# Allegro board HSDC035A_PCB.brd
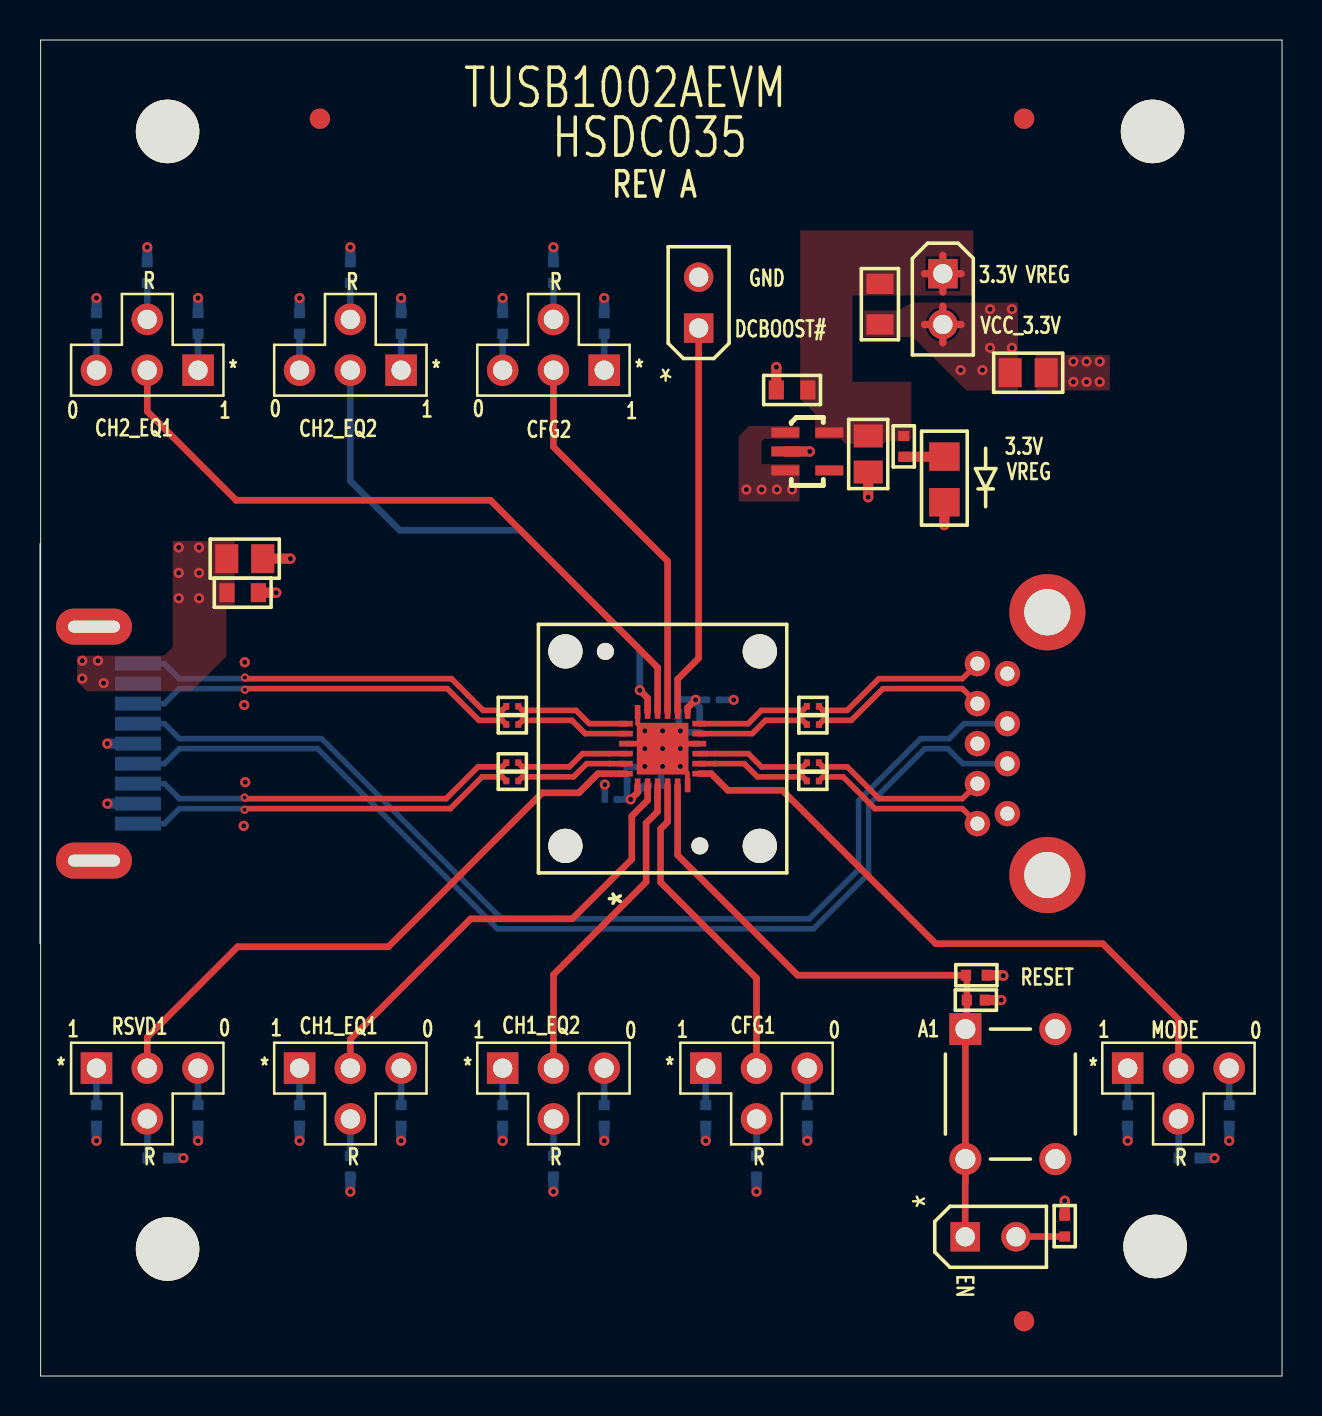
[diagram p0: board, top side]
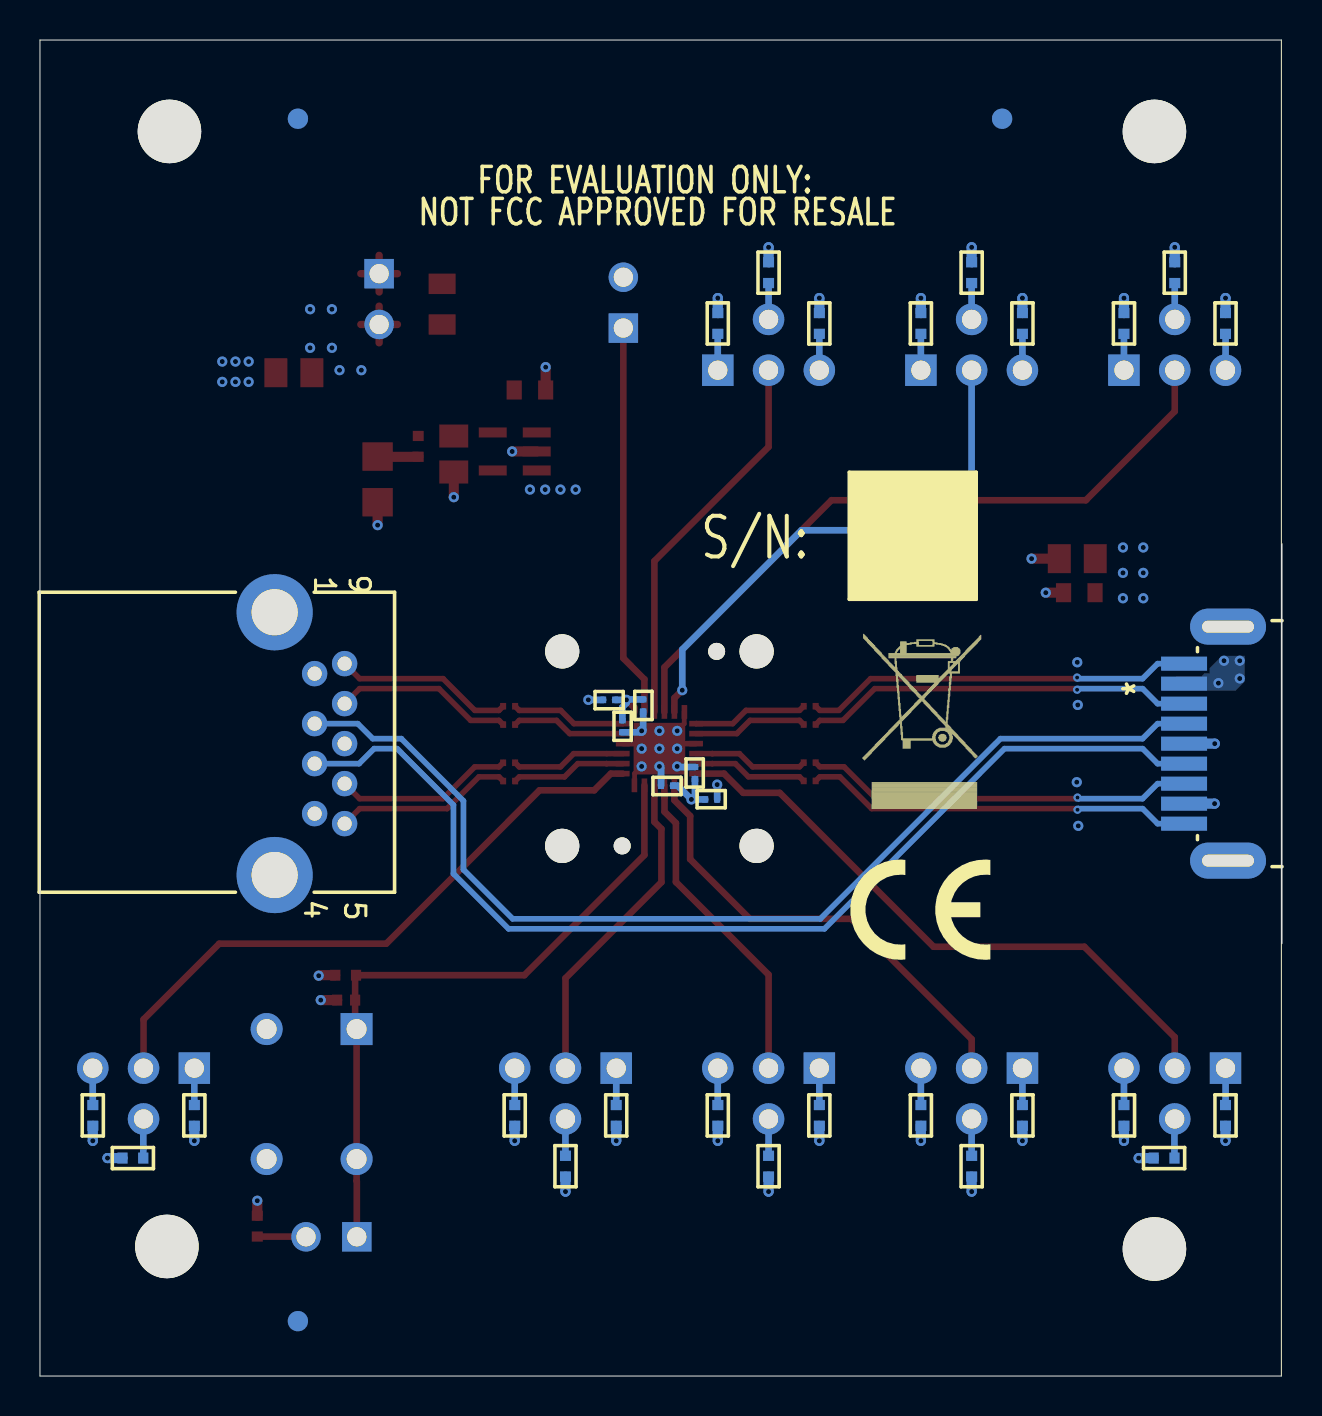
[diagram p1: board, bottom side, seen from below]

Outline 62.14 x 66.8 mm; copper layers: TOP, L2_GND, L3_PWR, BOTTOM. Coordinates in mm from the lower left corner of the outline.
Outline path: 0.03,66.8 62.14,66.8 62.14,0 0.03,0 0.03,66.8

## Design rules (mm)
net group DIFFPAIR0: nets N16632710 N16632722
net group DIFFPAIR2: nets USB2_DM USB2_DP
net group DIFFPAIR4: nets TX2N_CONN TX2P_CONN
net group DIFFPAIR5: nets TX1N TX1P
net group DIFFPAIR6: nets TX2N TX2P
net group DIFFPAIR7: nets N16640066 N16640078
net group DIFFPAIR8: nets N16640110 N16640114
net group DIFFPAIR9: nets N16640070 N16640074
net group DIFFPAIR10: nets N16640102 N16640106

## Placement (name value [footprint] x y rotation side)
C1  0.1uF  [C0201]  23.63 30.67 0 top
C2  0.1uF  [C0201]  23.63 29.75 0 top
C3  0.1uF  [C0201]  38.67 33.49 0 top
C4  0.1uF  [C0201]  38.67 32.57 0 top
C5  10uF  [C0805]  10.24 40.87 0 top
C6  10uF  [C0805]  41.44 46.1 270 top
C7  1uf  [C0603]  10.14 39.17 0 top
C8  1uf  [C0603]  37.63 49.3 180 top
C9  1uF  [C0201]  29.37 30.15 90 bottom
C10  1uF  [C0201]  33 32.49 270 bottom
C11  0.1uF  [C0201]  30.77 29.51 0 bottom
C12  0.1uF  [C0201]  33.66 33.81 0 bottom
C13  0.01uF  [C0201]  28.56 28.83 180 bottom
C14  0.01uF  [C0201]  31.96 33.53 270 bottom
C15  22uF  [C0805]  49.44 50.16 0 top
C16  220nF  [C0402]  46.82 18.8 0 top
C17  220nF  [C0201]  38.67 30.66 0 top
C18  220nF  [C0201]  38.67 29.75 0 top
C19  220nF  [C0201]  23.63 33.49 0 top
C20  220nF  [C0201]  23.63 32.57 0 top
D1  LED Green 0805  [LED_0805]  45.25 44.83 90 top
J1  HDR2X1 M .1  [HDR_THVT_1X2_100]  46.29 6.96 90 top
J2  HDR2X1 M .1  [HDR_THVT_1X2_100]  32.95 52.4 180 top
J3  HDR2X1 M .1  [HDR_THVT_1X2_100]  45.17 55.12 0 top
JMP1  4 Pin-T Berg Jumper  [BERG2X3TEE]  12.99 15.39 0 top
JMP2  4 Pin-T Berg Jumper  [BERG2X3TEE]  23.15 15.39 0 top
JMP3  4 Pin-T Berg Jumper  [BERG2X3TEE]  33.31 15.39 0 top
JMP4  4 Pin-T Berg Jumper  [BERG2X3TEE]  54.41 15.39 0 top
JMP5  4 Pin-T Berg Jumper  [BERG2X3TEE]  7.91 50.29 180 top
JMP6  4 Pin-T Berg Jumper  [BERG2X3TEE]  18.07 50.29 180 top
JMP7  4 Pin-T Berg Jumper  [BERG2X3TEE]  2.83 15.39 0 top
JMP8  4 Pin-T Berg Jumper  [BERG2X3TEE]  28.23 50.29 180 top
NOREF  -  []  0.03 66.8 0 top
NOREF#2  -  [unnamed#2]  49.23 2.74 0 top
NOREF#3  -  [unnamed#2]  14 62.87 0 top
NOREF#4  -  []  0.03 0 0 top
NOREF#5  -  []  12.66 0.86 0 top
NOREF#6  -  []  62.14 0 90 top
NOREF#7  -  []  88.93 38.1 0 top
NOREF#8  -  [unnamed#2]  49.23 62.87 0 top
NOREF#9  -  [unnamed#2]  6.38 6.35 0 top
NOREF#10  -  [unnamed#2]  6.38 62.23 0 top
NOREF#11  -  [unnamed#2]  55.66 62.23 0 top
NOREF#12  -  [unnamed#2]  55.79 6.48 0 top
NOREF#13  -  []  -3.78 -69.85 0 top
NOREF#14  -  []  18.09 23.32 180 bottom
NOREF#15  -  [unnamed#2]  14 62.87 180 bottom
NOREF#16  -  []  28.63 42.01 180 bottom
NOREF#17  -  [unnamed#2]  49.23 2.74 180 bottom
NOREF#18  -  [unnamed#2]  49.23 62.87 180 bottom
NOREF#19  -  []  17.99 33.93 180 bottom
NOREF#20  -  []  30.92 5.31 180 bottom
P1  USB3_STANDARD_TYPE_A_PLUG  [CON_SMRT_USB3A_AMP]  2.7 31.62 90 bottom
P2  USB3 Type A Receptacle  [USB3_TYPEA]  46.9 31.62 270 bottom
R1  1k  [R0402]  12.99 13.03 270 bottom
R2  20k  [R0402]  15.53 10.49 270 bottom
R3  1k  [R0402]  18.07 13.03 270 bottom
R4  1k  [R0402]  23.15 13.03 270 bottom
R5  20k  [R0402]  25.69 10.49 270 bottom
R6  1k  [R0402]  28.23 13.03 270 bottom
R7  1k  [R0402]  7.91 52.63 90 bottom
R8  20k  [R0402]  5.37 55.17 90 bottom
R9  1k  [R0402]  2.83 52.63 90 bottom
R10  1k  [R0402]  18.07 52.63 90 bottom
R11  20k  [R0402]  15.53 55.17 90 bottom
R12  1k  [R0402]  12.99 52.63 90 bottom
R13  1k  [R0402]  33.31 13.03 270 bottom
R14  20k  [R0402]  35.85 10.49 270 bottom
R15  1k  [R0402]  38.39 13.03 270 bottom
R16  1k  [R0402]  2.83 13.03 270 bottom
R17  20k  [R0402]  5.9 10.9 0 bottom
R18  1k  [R0402]  7.91 13.03 270 bottom
R19  1k  [R0402]  54.41 13.03 270 bottom
R20  20k  [R0402]  57.49 10.9 0 bottom
R21  1k  [R0402]  59.49 13.03 270 bottom
R22  1k  [R0402]  28.23 52.63 90 bottom
R23  20k  [R0402]  25.69 55.17 90 bottom
R24  1k  [R0402]  23.15 52.63 90 bottom
R25  1k  [R0402]  51.26 7.49 90 top
R26  0 Ohm  [R0805]  42.02 53.59 270 top
R27  20k  [R0402]  46.85 20.04 180 top
R28  300 Ohm  [R0402]  43.21 46.48 270 top
SW1  Switch - Push Button  [SW_THVT_EVQPAX05]  48.55 14.1 0 top
U1  TUSB1002ARGE  [SKT_TUSB1002RGE]  31.15 31.37 90 top
U2  LP5907  [DBV_R-PDSO-G5]  38.39 46.23 0 top

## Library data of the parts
C1-C4 C9-C14 C17-C20 = cc0201
C5 C6 C15 = cc0805
C7 C8 = cc0603 1.0uf 25V
C16 = cc0402
D1 = LED Green 0805_0
J1-J3 = HDR2X1 M .1
JMP1-JMP8 = 4 Pin-T Berg Jumper_0
P1 = USB3_STANDARD_TYPE_A_PLUG_0
P2 = USB 3.0 Type A Receptacle
R1-R25 R27 R28 = r0402
R26 = r0805
SW1 = Switch - Push Button_0
U1 = TUSB1002RGE_0
U2 = LP5907

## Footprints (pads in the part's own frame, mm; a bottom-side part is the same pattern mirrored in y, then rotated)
BERG2X3TEE
  rect 1.575x1.575 hole 0.965: 1(0,0)
  round 1.575 hole 0.965: 2(2.54,0) 3(5.08,0) 4(2.54,-2.54)
C0201
  rect 0.3x0.33 smd: 1(-0.3,0) 2(0.3,0)
C0402
  rect 0.51x0.55 smd: 1(-0.45,0) 2(0.45,0)
C0603
  rect 0.76x0.95 smd: 1(-0.787,0) 2(0.787,0)
C0805
  rect 1.15x1.45 smd: 1(-0.9,0) 2(0.9,0)
CON_SMRT_USB3A_AMP
  rect 0.7x2.3 smd: 1(3,2.2) 2(1,2.2) 3(-1,2.2) 4(-3,2.2) 5(-4,2.2) 6(-2,2.2) 7(0,2.2) 8(2,2.2) 9(4,2.2)
  oval 1.8x3.8 hole 0.6x2.6: 10(-5.85,0) 11(5.85,0)
DBV_R-PDSO-G5
  rect 1.4x0.5 smd: 1(-1.1,0.95) 2(-1.1,0) 3(-1.1,-0.95) 4(1.1,-0.95) 5(1.1,0.95)
HDR_THVT_1X2_100
  rect 1.473x1.473 hole 0.965: 1(0,0)
  round 1.473 hole 0.965: 2(0,-2.54)
LED_0805
  rect 1.422x1.524 smd: 1(-1.143,0) 2(1.143,0)
R0402
  rect 0.51x0.55 smd: 1(-0.52,0) 2(0.52,0)
R0805
  rect 1.02x1.35 smd: 1(-1.016,0) 2(1.016,0)
SKT_TUSB1002RGE
  round 1.71 hole 1.71 unplated: (-4.863,4.863) (-4.863,-4.863) (4.863,4.863) (4.863,-4.863)
  round 0.85 hole 0.85 unplated: (-4.863,-1.863) (4.863,2.863)
  rect 0.69x0.28 smd: 1(-1.835,1.25) 2(-1.835,0.75) 3(-1.835,0.25) 4(-1.835,-0.25) 5(-1.835,-0.75) 6(-1.835,-1.25) 13(1.835,-1.25) 14(1.835,-0.75) 15(1.835,-0.25) 16(1.835,0.25) 17(1.835,0.75) 18(1.835,1.25)
  rect 0.28x0.69 smd: 7(-1.25,-1.835) 8(-0.75,-1.835) 9(-0.25,-1.835) 10(0.25,-1.835) 11(0.75,-1.835) 12(1.25,-1.835) 19(1.25,1.835) 20(0.75,1.835) 21(0.25,1.835) 22(-0.25,1.835) 23(-0.75,1.835) 24(-1.25,1.835)
  rect 2.58x2.58 smd: 25(0,0)
SW_THVT_EVQPAX05
  rect 1.6x1.6 hole 1: A1(-2.25,3.25)
  round 1.6 hole 1: A2(-2.25,-3.25) B1(2.25,3.25) B2(2.25,-3.25)
unnamed#2
  round 1.016 smd: (0,0)
USB3_TYPEA
  round 1.27 hole 0.711: 1(-3.5,-1.5) 2(-1,-1.5) 3(1,-1.5) 4(3.5,-1.5) 5(4,0) 6(2,0) 7(0,0) 8(-2,0) 9(-4,0)
  round 3.81 hole 2.311: 10(-6.57,-3.5) 11(6.57,-3.5)

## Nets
3.3V: C6.1 C8.1 J3.1 R26.1 R28.1 U2.5(VOUT)
GND: C5.2 C6.2 C7.2 C8.2 C9.2 C10.2 C11.2 C12.2 C13.2 C14.2 C15.2 C16.2 D1.1(CATHODE) J2.2 P1.4(GND#4) P1.7(GND_SHIELD) P1.10(GND#10) P1.11(GND#11) P2.4(GND) P2.7(GND_DRAIN) P2.10(SHIELD1) P2.11(SHIELD2) R2.2 R3.2 R5.2 R6.2 R8.2 R9.2 R11.2 R12.2 R14.2 R15.2 R17.2 R18.2 R20.2 R21.2 R23.2 R24.2 R25.2 SW1.B1 SW1.B2(B) U1.6(GND#6) U1.10(GND#10) U1.18(GND#18) U1.21(GND#21) U1.25(PAD) U2.2(GND)
VBUS: C5.1 C7.1 P1.1(VBUS) P2.1(VBUS) U2.1(VIN) U2.3(EN)
VCC_3.3V: C9.1 C10.1 C11.1 C12.1 C13.1 C14.1 C15.1 J3.2 R1.2 R4.2 R7.2 R10.2 R13.2 R16.2 R19.2 R22.2 R26.2 R27.1 U1.1(VCC#1) U1.13(VCC#13)
CFG1: JMP3.2 U1.4(CFG1)
CFG2: JMP8.2 U1.15(CFG2)
CH1_EQ1: JMP1.2 U1.2(CH1_EQ1)
CH1_EQ2: JMP2.2 U1.3(CH1_EQ2)
CH2_EQ1: JMP5.2 U1.16(CH2_EQ1)
CH2_EQ2: JMP6.2 U1.17(CH2_EQ2)
DCBOOST#: J2.1 U1.14(DCBOOST#)
EN: C16.1 J1.1 R27.2 SW1.A1 SW1.A2(A) U1.5(EN)
MODE: JMP4.2 U1.7(MODE)
RSVD1: JMP7.2 U1.24(RSVD1)
TX1N: C2.2 U1.23(TX1N)
TX1P: C1.2 U1.22(TX1P)
TX2N: C4.1 U1.11(TX2N)
TX2N_CONN: C4.2 P2.8(SS_TX_N)
TX2P: C3.1 U1.12(TX2P)
TX2P_CONN: C3.2 P2.9(SS_TX_P)
USB2_DM: P1.2(DM) P2.2(USB2_DM)
USB2_DP: P1.3(DP) P2.3(USB2_DP)
N04063: JMP1.1 R1.1
N04069: JMP1.4 R2.1
N04079: JMP1.3 R3.1
N04162: JMP2.1 R4.1
N04168: JMP2.4 R5.1
N04172: JMP2.3 R6.1
N04828: JMP3.4 R14.1
N05600: JMP7.4 R17.1
N05896: J1.2 R25.1
N16532433: D1.2(ANNODE) R28.2
N16632710: C2.1 P1.5(SSRXN)
N16632722: C1.1 P1.6(SSRXP)
N16635768: JMP3.3 R15.1
N16635786: JMP3.1 R13.1
N16636225: JMP4.4 R20.1
N16636229: JMP4.1 R19.1
N16636241: JMP4.3 R21.1
N16636785: JMP5.4 R8.1
N16636789: JMP5.3 R9.1
N16636801: JMP5.1 R7.1
N16637091: JMP6.1 R10.1
N16637103: JMP6.3 R12.1
N16637121: JMP6.4 R11.1
N16637440: JMP7.1 R16.1
N16637452: JMP7.3 R18.1
N16637756: JMP8.1 R22.1
N16637768: JMP8.3 R24.1
N16637780: JMP8.4 R23.1
N16640066: C19.2 U1.19(RX2P)
N16640070: C19.1 P1.9(SSTXP)
N16640074: C20.1 P1.8(SSTXN)
N16640078: C20.2 U1.20(RX2N)
N16640102: C17.2 P2.6(SS_RX_P)
N16640106: C18.2 P2.5(SS_RX_N)
N16640110: C18.1 U1.8(RX1N)
N16640114: C17.1 U1.9(RX1P)

Pads without a net: U2 4

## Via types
v1: diameter 0.406, hole 0.203, TOP to BOTTOM, 4 vias
v2: diameter 0.508, hole 0.254, TOP to BOTTOM, 79 vias

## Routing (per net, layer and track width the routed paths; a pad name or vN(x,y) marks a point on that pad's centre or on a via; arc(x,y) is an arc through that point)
3.3V: length 3.7
  TOP w0.368: 44.25,55.12 J3.1 ; J3.1 46.08,55.12 ; J3.1 45.17,56.03 ; J3.1 45.17,54.2
GND: length 75.7
  TOP w0.241: U1.18 29.91,33.2 29.91,32.61 v2(30.26,32.26) ; v2(32.04,30.48) 32.39,30.13 32.39,29.54 U1.6
  TOP w0.279: U1.10 32.29,31.62 v2(32.04,31.37) ; v2(30.26,31.37) 30.21,31.37 29.96,31.62 U1.21
  TOP w0.508: D1.1 v2(45.25,42.55) ; C16.2 v2(48.09,18.8) ; R25.2 v2(51.26,8.76) ; v2(36.84,50.44) 36.84,50.44 C8.2 ; C5.2 v2(12.53,40.87) ; C7.2 v2(11.82,39.17) ; C6.2 v2(41.44,43.94) ; U2.2 v2(38.51,46.23)
  L2_GND w0.241: P1.11 4.78,37.47 ; P1.11 2.7,38.55 ; P1.11 2.7,36.39 ; 48.4,27.31 P2.4 ; P2.4 49.21,28.12 ; P2.4 48.4,28.93 ; 2.7,25.77 2.7,26.85 ; 2.7,25.77 2.7,24.69 ; 2.7,25.77 4.78,25.77 ; SW1.B2 51.78,10.85 ; SW1.B2 49.82,10.85 ; SW1.B2 50.8,11.83 ; SW1.B2 50.8,9.87 ; P2.7 46.9,32.43 ; P2.7 46.9,30.81 ; P2.7 47.71,31.62 ; P2.7 46.08,31.62 ; 50.4,36.11 P2.10 ; P2.10 50.4,40.27 ; P2.10 48.31,38.19 ; P2.10 52.48,38.19 ; 50.4,22.97 P2.11 ; P2.11 48.31,25.05 ; P2.11 52.48,25.05 ; P2.11 50.4,27.13 ; 32.04,54.94 J2.2 ; J2.2 33.87,54.94 ; J2.2 32.95,55.86 ; J2.2 32.95,54.03 ; SW1.B1 50.8,18.33 ; SW1.B1 50.8,16.37 ; SW1.B1 49.82,17.35 ; SW1.B1 51.78,17.35
  BOTTOM w0.33: C13.2 v2(28.26,29.57) ; C9.2 30.23,30.45 v2(30.26,30.48) ; C10.2 32.11,32.19 v2(32.04,32.26) 31.96,32.33 C14.2 ; C11.2 31.07,30.4 v2(31.15,30.48) ; C12.2 v2(34.7,33.81)
  BOTTOM w0.508: R6.2 v2(28.23,11.76) ; R17.2 v2(7.17,10.9) ; R24.2 v2(23.15,53.9) ; R20.2 v2(58.76,10.9) ; R14.2 v2(35.85,9.22) ; R23.2 v2(25.69,56.44) ; R8.2 v2(5.37,56.44) ; R2.2 v2(15.53,9.22) ; P1.4 v2(3.37,28.62) ; R15.2 v2(38.39,11.76) ; R18.2 v2(7.91,11.76) ; R21.2 v2(59.49,11.76) ; R9.2 v2(2.83,53.9) ; R11.2 v2(15.53,56.44) ; R12.2 v2(12.99,53.9) ; R5.2 v2(25.69,9.22) ; R3.2 v2(18.07,11.76) ; P1.7 v2(3.37,31.62)
  vias: v2(10.24,35.69) v2(10.22,33.55) v2(10.27,29.69) v2(10.19,27.51) v2(31.15,32.26) v2(31.15,31.37) v2(51.7,50.72) v2(51.7,49.71) v2(52.36,50.72) v2(52.36,49.71) v2(53.02,50.72) v2(53.02,49.71)
VBUS: length 2.4
  L3_PWR w0.368: P2.1 48.4,35.93 ; P2.1 49.21,35.12 ; P2.1 48.4,34.31
  vias: v2(2.12,35.76) v2(2.12,34.87) v2(2.9,35.76) v2(3.18,34.65) v2(6.94,41.43) v2(6.94,40.16) v2(6.94,38.89) v2(7.96,41.43) v2(7.96,40.16) v2(7.96,38.89) v2(35.34,44.32) v2(36.1,44.32) v2(36.86,44.32) v2(37.63,44.32)
VCC_3.3V: length 21.3
  TOP w0.33: U1.1 29.9,29.18 v2(29.55,28.83) ; v2(32.8,33.81) 32.4,33.41 U1.13
  TOP w0.368: 44.25,52.58 J3.2 ; J3.2 46.08,52.58 ; J3.2 45.17,51.66 ; J3.2 45.17,53.49
  TOP w0.508: v2(48.19,20.02) 48.17,20.04 R27.1
  L3_PWR w0.368: J3.2 46.08,52.58 ; J3.2 45.17,53.49 ; J3.2 44.25,52.58 ; J3.2 45.17,51.66
  BOTTOM w0.33: v2(32.8,33.81) 32.8,33.81 C12.1 ; v2(32.8,33.81) 32.8,33.64 33,33.44 C10.1 ; v2(32.8,33.81) 32.78,33.83 C14.1 ; C13.1 v2(29.55,28.83) ; v2(29.55,28.83) 30.23,29.51 C11.1 ; v2(29.55,28.83) 29.37,29.01 C9.1
  BOTTOM w0.508: R7.2 v2(7.91,53.9) ; R10.2 v2(18.07,53.9) ; R13.2 v2(33.31,11.76) ; R22.2 v2(28.23,53.9) ; R16.2 v2(2.83,11.76) ; R19.2 v2(54.41,11.76) ; R1.2 v2(12.99,11.76) ; R4.2 v2(23.15,11.76)
  vias: v2(46.06,50.29) v2(47.15,50.29) v2(47.53,53.34) v2(47.53,51.41) v2(48.62,53.34) v2(48.62,51.41)
CFG1: length 16.3
  TOP w0.33: JMP3.2 35.85,19.89 31.05,24.69 31.05,27.36 31.4,27.71 U1.4
CFG2: length 19.5
  TOP w0.33: U1.15 31.4,40.75 25.69,46.46 JMP8.2
CH1_EQ1: length 23.3
  TOP w0.33: U1.2 30.4,28.79 29.61,28 29.61,25.84 26.63,22.86 21.55,22.86 15.53,16.84 JMP1.2
CH1_EQ2: length 16.3
  TOP w0.33: U1.3 30.9,28.92 30.89,28.92 30.89,28.22 30.32,27.65 30.32,24.7 25.69,20.07 JMP2.2
CH2_EQ1: length 35.1
  TOP w0.33: U1.16 30.9,35.43 22.54,43.79 9.81,43.79 5.37,48.23 JMP5.2
CH2_EQ2: length 26.8
  TOP w0.33: v2(30.01,34.29) 30.4,33.9 U1.17
  BOTTOM w0.33: v2(30.01,34.29) 30.01,36.32 24.04,42.29 17.99,42.29 15.53,44.75 JMP6.2
DCBOOST#: length 19.6
  TOP w0.33: U1.14 31.9,34.84 32.95,35.89 J2.1
EN: length 33.5
  TOP w0.33: U1.5 31.9,26.05 37.9,20.04 R27.2 46.37,20 C16.1 46.37,17.42 SW1.A1 SW1.A2 46.3,9.75 46.29,9.74 J1.1
MODE: length 31.5
  TOP w0.33: JMP4.2 56.95,17.83 53.17,21.62 44.81,21.62 37.14,29.29 34.41,29.29 33.58,30.12 U1.7
RSVD1: length 31
  TOP w0.33: JMP7.2 5.37,16.94 9.89,21.46 17.43,21.46 25.13,29.16 26.95,29.16 27.91,30.12 U1.24
TX1N: length 5.7
  TOP w0.279: C2.2 24.14,29.96 26.69,29.96 27.35,30.62 28.5,30.62 28.5,30.62 U1.23
TX1P: length 5.7
  TOP w0.279: U1.22 28.5,31.12 28.5,31.12 27.14,31.12 26.49,30.46 24.14,30.46 C1.2
TX2N: length 5.7
  TOP w0.279: C4.1 38.16,32.78 36.29,32.78 35.63,32.12 U1.11
TX2N_CONN: length 9
  TOP w0.279: C4.2 39.17,32.78 40.59,32.78 42.17,34.37 46.15,34.37 P2.8
TX2P: length 5.7
  TOP w0.279: C3.1 38.16,33.28 36.09,33.28 35.42,32.62 U1.12
TX2P_CONN: length 9
  TOP w0.279: P2.9 46.15,34.87 41.97,34.87 40.38,33.28 39.17,33.28 C3.2
USB2_DM: length 53.6
  BOTTOM w0.279: P1.2 6.22,32.62 6.97,31.87 14.09,31.87 23.1,22.86 38.49,22.86 40.95,25.32 40.95,28.76 44.06,31.87 45.49,31.87 46.24,32.62 P2.2
USB2_DP: length 53.6
  BOTTOM w0.279: P2.3 46.17,30.62 45.42,31.37 44.27,31.37 41.45,28.55 41.45,25.12 38.7,22.36 22.89,22.36 13.88,31.37 6.97,31.37 6.22,30.62 P1.3
N04063: length 1.8
  BOTTOM w0.33: R1.1 JMP1.1
N04069: length 1.8
  BOTTOM w0.33: R2.1 JMP1.4
N04079: length 1.8
  BOTTOM w0.33: R3.1 JMP1.3
N04162: length 1.8
  BOTTOM w0.33: R4.1 JMP2.1
N04168: length 1.8
  BOTTOM w0.33: R5.1 JMP2.4
N04172: length 1.8
  BOTTOM w0.33: R6.1 JMP2.3
N04828: length 1.8
  BOTTOM w0.33: R14.1 JMP3.4
N05600: length 2
  BOTTOM w0.33: JMP7.4 5.38,12.84 R17.1
N05896: length 2.4
  TOP w0.33: J1.2 48.84,6.97 R25.1
N16532433: length 2
  TOP w0.508: D1.2 45.23,45.96 R28.2
N16632710: length 19.5
  TOP w0.279: C2.1 23.12,29.96 22.12,29.96 20.53,28.37 10.29,28.37 v1(10.23,28.31)
  BOTTOM w0.279: v1(10.23,28.31) 10.18,28.37 6.97,28.37 6.22,27.62 P1.5
N16632722: length 19.5
  TOP w0.279: v1(10.23,28.92) 10.29,28.87 20.32,28.87 21.91,30.46 23.12,30.46 C1.1
  BOTTOM w0.279: v1(10.23,28.92) 10.18,28.87 6.97,28.87 6.22,29.62 P1.6
N16635768: length 1.8
  BOTTOM w0.33: R15.1 JMP3.3
N16635786: length 1.8
  BOTTOM w0.33: R13.1 JMP3.1
N16636225: length 2
  BOTTOM w0.33: JMP4.4 56.97,12.84 R20.1
N16636229: length 1.8
  BOTTOM w0.33: R19.1 JMP4.1
N16636241: length 1.8
  BOTTOM w0.33: R21.1 JMP4.3
N16636785: length 1.8
  BOTTOM w0.33: R8.1 JMP5.4
N16636789: length 1.8
  BOTTOM w0.33: R9.1 JMP5.3
N16636801: length 1.8
  BOTTOM w0.33: R7.1 JMP5.1
N16637091: length 1.8
  BOTTOM w0.33: R10.1 JMP6.1
N16637103: length 1.8
  BOTTOM w0.33: R12.1 JMP6.3
N16637121: length 1.8
  BOTTOM w0.33: R11.1 JMP6.4
N16637440: length 1.8
  BOTTOM w0.33: R16.1 JMP7.1
N16637452: length 1.8
  BOTTOM w0.33: R18.1 JMP7.3
N16637756: length 1.8
  BOTTOM w0.33: R22.1 JMP8.1
N16637768: length 1.8
  BOTTOM w0.33: R24.1 JMP8.3
N16637780: length 1.8
  BOTTOM w0.33: R23.1 JMP8.4
N16640066: length 5.7
  TOP w0.279: C19.2 24.14,33.28 26.82,33.28 27.48,32.62 U1.19
N16640070: length 19.5
  TOP w0.279: v1(10.25,34.92) 10.31,34.87 20.58,34.87 22.17,33.28 23.12,33.28 C19.1
  BOTTOM w0.279: v1(10.25,34.92) 10.2,34.87 6.97,34.87 6.22,35.62 P1.9
N16640074: length 19.5
  TOP w0.279: C20.1 23.12,32.78 21.96,32.78 20.38,34.37 10.31,34.37 v1(10.25,34.31)
  BOTTOM w0.279: P1.8 6.22,33.62 6.97,34.37 10.2,34.37 v1(10.25,34.31)
N16640078: length 5.7
  TOP w0.279: U1.20 27.27,32.12 26.61,32.78 24.14,32.78 C20.2
N16640102: length 9
  TOP w0.279: P2.6 46.15,28.87 41.97,28.87 40.39,30.46 39.17,30.46 C17.2
N16640106: length 9
  TOP w0.279: C18.2 39.17,29.96 40.18,29.96 41.77,28.37 46.15,28.37 P2.5
N16640110: length 5.7
  TOP w0.279: C18.1 38.16,29.96 35.89,29.96 35.23,30.62 33.79,30.62 33.79,30.62 U1.8
N16640114: length 5.7
  TOP w0.279: U1.9 33.39,31.12 33.79,31.12 35.44,31.12 36.1,30.46 38.16,30.46 C17.1

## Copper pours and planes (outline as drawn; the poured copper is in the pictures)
3.3V on TOP: 43.47,46.74 42.32,46.74 42.2,46.61 40.29,46.61 40.04,46.86 38.77,46.86 38.77,48.13 38.03,48.87 38.03,57.28 46.69,57.28 46.69,54.03 40.65,54.03 40.65,49.71 43.59,49.71 43.59,46.86
GND on TOP: 49.82,51.05 49.82,49.28 53.53,49.28 53.53,51.05
GND on L2_GND: 50.31,0.64 0.67,0.64 0.67,66.17 61.5,66.17 61.5,0.64 50.32,0.64
VBUS on TOP: 38.01,47.5 38.01,46.86 36.23,46.86 36.1,46.74 36.1,45.59 38.01,45.59 38.01,43.71 34.96,43.71 34.96,46.99 35.47,47.5
VBUS on TOP: 2.34,34.24 1.86,34.72 1.86,36.02 6.21,36.02 6.64,36.45 6.64,41.76 9.74,41.76 9.74,38.53 9.33,38.53 9.33,35.99 7.58,34.24
VBUS on BOTTOM: 5.29,34.98 4.05,34.98 3,36.02 1.86,36.02 1.86,34.72 2.32,34.26 5.29,34.26
VBUS on L3_PWR: 6.38,38.46 6.38,45.72 49.82,45.72 49.82,33.99 45.5,33.99 45.5,42.67 9.74,42.67 9.74,38.46
VCC_3.3V on TOP: 41.23,53.29 42.91,53.29 43.64,53.67 48.93,53.67 48.93,49.28 46.34,49.28 43.67,51.94 41.23,51.94
VCC_3.3V on L3_PWR: 50.31,0.64 0.67,0.64 0.67,66.17 61.5,66.17 61.5,0.64 50.32,0.64

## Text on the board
BOTTOM: LAYER 4 - BOTTOM SIDE
Board Geometry/Soldermask Bottom: SOLDERMASK BOTTOM
Package Geometry/Pastemask Bottom: PASTEMASK BOTTOM
Ref Des/Silkscreen Bottom: FOR EVALUATION ONLY: | NOT FCC APPROVED FOR RESALE | SILKSCREEN BOTTOM
TOP: LAYER 1 - TOP SIDE
Board Geometry/Soldermask Top: SOLDERMASK TOP
Package Geometry/Pastemask Top: PASTEMASK TOP
Ref Des/Silkscreen Top: * | 0 | 1 | CH2_EQ1 | RSVD1 | R | CH2_EQ2 | CH1_EQ1 | CH1_EQ2 | CFG2 | CFG1 | DCBOOST# | GND | 3.3V VREG | VCC_3.3V | 3.3V | VREG | RESET | MODE | EN | REV A | SILKSCREEN TOP | TUSB1002AEVM | HSDC035
L2_GND: LAYER 2 - GND PLANE
L3_PWR: LAYER 3 - PWR PLANE
XSECTION_CHART: * AIR 0 MIL | * SOLDERMASK-0.8MIL 0.8 MIL | L1: COPPER_1/2OZ_PLATED 1.4 MIL | * FILL_0.200 7.87 MIL | L2: COPPER_1.0OZ 1.4 MIL | * CORE_1.00 39.37 MIL | L3: COPPER_1.0OZ 1.4 MIL | L4: COPPER_1/2OZ_PLATED 1.4 MIL | DESIGN CROSS SECTION CHART | ___________________________ | TOTAL THICKNESS 62.31 MIL | 1-4
DIMENSION: FABRICATION DRAWING | CAD ORIGIN
User.7: LAYER 1 | LAYER 2 | LAYER 3 | LAYER 4 | LAYER | NO. | TABLE 1: | TOP | L2_GND | L3_PWR | BOTTOM | NAME | DIFFIRENTIAL PAIR | IMPEDANCE (OHMS) | 90  +/- 10% | DIFF TRACE | WIDTH | 0.011" | SPACING | 0.00866" | SINGLE ENDED | 50 +/- 10% | TRACE WIDTH | 0.013" | REFERENCE | SPECIAL FAB NOTES: | PLACE DRILL CHART HERE: | 1:FAB SHOP MUST FOLLOW THE SOLDER MASK REVIEW LAYERS. | 2: | DANGLING VIA | ITEM | QTY | 4 | GND | NET | MIN. ANNULAR RING 2 MIL EXTERNAL PER IPC-6012C CLASS 2 | REGISTRATION TOLERANCES: METAL +/- X MIL,HOLES +/- X MIL | IMPEDANCE CONTROL: | BOARD SIZE (REFER ALSO ARRAY/PANEL PROFILING INFORMATION) | MIXED DIELECTRIC: | LAMINATE MATERIAL: | THICKNESS: | TOLERANCE: | COPPER THICKNESS (FINISHED): | BOARD FINISH: | NUMBER OF LAYERS: | MIN. TRACK WIDTH: | MIN. CLEARANCE  : | MIN. VIA PAD/DRILL: | THIEVING ALLOWED: | X | OUTER: | INNER SIGNAL: | INNER PLANE: | OTHER: | SILKSCREEN: | SOLDERMASK: (PER IPC-6011,6012) | BOARD SURFACE TREATMENT: | ADDITIONAL REQUIREMENTS: | VENDOR MARKING: | SILKSCREEN COLOR: | SOLDERMASK COLOR: | THROUGH-HOLE VIA TREATMENT: | VIA FILL USING NON-CONDUCTIVE EPOXY: | FOR WIRE BONDING: | VENDOR DATE CODE,UL,LOGO: | FR-4 HIGH Tg | 0.062" +/-10% | IPC-6012C TYPE 3 CLASS 2 | OTHER +/- | MICRO-SECTION | CERTIFICATES OF COMPLIANCE | NICKEL/GOLD (ENIG) | IMMERSION TIN | HARD GOLD | IN AN OPEN AREA | 1/4 OZ. | OPEN | NO | 11 MIL | 8.66 MIL | 16/08 MIL | NONE | DESIGN INFORMATION | ROGERS 4350B | 0.093" +/-10% | YES | TDR REPORTS/COUPONS | WHITE | GREEN | SOFT GOLD | TENTED | 1/2 OZ. | BOW & TWIST: | ORGANIC (OSP) | OTHER | WHERE INDICATED (SEE DRAWING) | YES - SEE TABLE 1 | ETCH | IDENTIFIER: | BLUE | RoHS | 1.0 OZ. | SILKSCREEN | PER SUPPLIED ARTWORK | ALL x MIL VIAS | ELECTRICAL TEST | UL 94V-0 | HASL | 2.0 OZ. | BREAK-AWAY | ENEPIG
User.13: FIGURE | SIZE | 8.0 | 10.0 | 28.0 | 38.0 | 39.37 | 91.0 | 33.46 | 67.32 | 125.0 | 102.36x23.62 | DRILL CHART: TOP to BOTTOM | ALL UNITS ARE IN MILS | TOLERANCE | +3.0/-3.0 | +2.0/-2.0 | PLATED | NON-PLATED | QTY | 4 | 79 | 9 | 38 | 2
